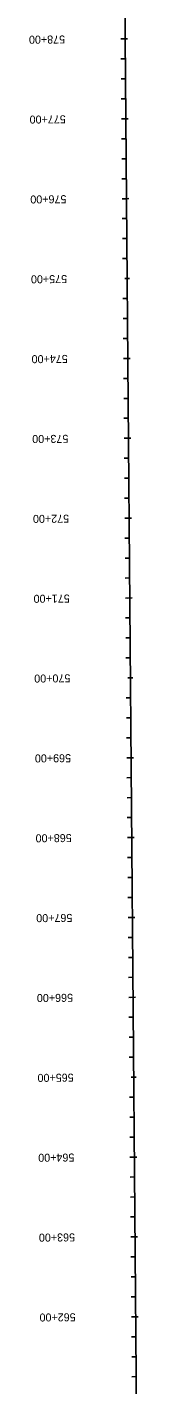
# Model space of a CAD drawing. Extents: x 23417911 to 23421158, y 6737892 to 6791804.
# Drawn here: x 23420741 to 23420889, y 6781685 to 6783385 of the extents above; entities that cross this region are included whole.
import ezdxf

# ---------------------------------------------------------------- set-up
doc = ezdxf.new("R2010")
doc.units = 0
for name, color, linetype in [('Alignment', 7, 'Continuous'), ('TextAlignmentLrg', 7, 'Continuous'), ('TextAlignmentSml', 7, 'Continuous')]:
    doc.layers.add(name, color=color, linetype=linetype)

msp = doc.modelspace()

# ---------------------------------------------------------------- linework, layer by layer
at = {"layer": 'Alignment'}
msp.add_line((23420888.7, 6779969.4), (23420840.8, 6785772.8), dxfattribs=at)
msp.add_line((23420888.7, 6779969.4), (23420840.8, 6785772.8), dxfattribs=at)
at = {"layer": 'TextAlignmentLrg'}
for p, q in [((23420860.7, 6783370.1), (23420855.2, 6783370.1)), ((23420861.5, 6783270.1), (23420856, 6783270.1)), ((23420862.3, 6783170.1), (23420856.8, 6783170.1)), ((23420860.1, 6783070.1), (23420866.2, 6783070.2)), ((23420864, 6782970.1), (23420858.5, 6782970.1)), ((23420864.8, 6782870.2), (23420859.3, 6782870.1)), ((23420865.6, 6782770.2), (23420860.1, 6782770.1)), ((23420866.4, 6782670.2), (23420861, 6782670.1)), ((23420864.2, 6782570.1), (23420870.3, 6782570.2)), ((23420868.1, 6782470.2), (23420862.6, 6782470.1)), ((23420868.9, 6782370.2), (23420863.4, 6782370.1)), ((23420869.7, 6782270.2), (23420864.3, 6782270.1)), ((23420870.6, 6782170.2), (23420865.1, 6782170.1)), ((23420868.3, 6782070.2), (23420874.4, 6782070.2)), ((23420872.2, 6781970.2), (23420866.7, 6781970.1)), ((23420873, 6781870.2), (23420867.6, 6781870.1)), ((23420873.9, 6781770.2), (23420868.4, 6781770.1))]:
    msp.add_line(p, q, dxfattribs=at)
at = {"layer": 'TextAlignmentSml'}
for p, q in [((23420857.6, 6783370.1), (23420863.7, 6783370.2)), ((23420860.9, 6783345.1), (23420855.4, 6783345.1)), ((23420861.1, 6783320.1), (23420855.6, 6783320.1)), ((23420861.3, 6783295.1), (23420855.8, 6783295.1)), ((23420858.4, 6783270.1), (23420864.5, 6783270.2)), ((23420861.7, 6783245.1), (23420856.2, 6783245.1)), ((23420861.9, 6783220.1), (23420856.4, 6783220.1)), ((23420862.1, 6783195.1), (23420856.6, 6783195.1)), ((23420859.2, 6783170.1), (23420865.4, 6783170.2)), ((23420862.5, 6783145.1), (23420857.1, 6783145.1)), ((23420862.7, 6783120.1), (23420857.3, 6783120.1)), ((23420862.9, 6783095.1), (23420857.5, 6783095.1)), ((23420860.1, 6783070.1), (23420866.2, 6783070.2)), ((23420863.3, 6783045.1), (23420857.9, 6783045.1)), ((23420863.5, 6783020.1), (23420858.1, 6783020.1)), ((23420863.8, 6782995.1), (23420858.3, 6782995.1)), ((23420860.9, 6782970.1), (23420867, 6782970.2)), ((23420864.2, 6782945.1), (23420858.7, 6782945.1)), ((23420864.4, 6782920.1), (23420858.9, 6782920.1)), ((23420864.6, 6782895.1), (23420859.1, 6782895.1)), ((23420861.7, 6782870.1), (23420867.8, 6782870.2)), ((23420865, 6782845.2), (23420859.5, 6782845.1)), ((23420865.2, 6782820.2), (23420859.7, 6782820.1)), ((23420865.4, 6782795.2), (23420859.9, 6782795.1)), ((23420862.5, 6782770.1), (23420868.7, 6782770.2)), ((23420865.8, 6782745.2), (23420860.4, 6782745.1)), ((23420866, 6782720.2), (23420860.6, 6782720.1)), ((23420866.2, 6782695.2), (23420860.8, 6782695.1)), ((23420863.4, 6782670.1), (23420869.5, 6782670.2)), ((23420866.6, 6782645.2), (23420861.2, 6782645.1)), ((23420866.8, 6782620.2), (23420861.4, 6782620.1)), ((23420867.1, 6782595.2), (23420861.6, 6782595.1)), ((23420864.2, 6782570.1), (23420870.3, 6782570.2)), ((23420867.5, 6782545.2), (23420862, 6782545.1)), ((23420867.7, 6782520.2), (23420862.2, 6782520.1)), ((23420867.9, 6782495.2), (23420862.4, 6782495.1)), ((23420865, 6782470.1), (23420871.1, 6782470.2)), ((23420868.3, 6782445.2), (23420862.8, 6782445.1)), ((23420868.5, 6782420.2), (23420863, 6782420.1)), ((23420868.7, 6782395.2), (23420863.2, 6782395.1)), ((23420865.8, 6782370.1), (23420872, 6782370.2)), ((23420869.1, 6782345.2), (23420863.7, 6782345.1)), ((23420869.3, 6782320.2), (23420863.9, 6782320.1)), ((23420869.5, 6782295.2), (23420864.1, 6782295.1)), ((23420866.7, 6782270.1), (23420872.8, 6782270.2)), ((23420869.9, 6782245.2), (23420864.5, 6782245.1)), ((23420870.1, 6782220.2), (23420864.7, 6782220.1)), ((23420870.4, 6782195.2), (23420864.9, 6782195.1)), ((23420867.5, 6782170.1), (23420873.6, 6782170.2)), ((23420870.8, 6782145.2), (23420865.3, 6782145.1)), ((23420871, 6782120.2), (23420865.5, 6782120.1)), ((23420871.2, 6782095.2), (23420865.7, 6782095.1)), ((23420868.3, 6782070.2), (23420874.4, 6782070.2)), ((23420871.6, 6782045.2), (23420866.1, 6782045.1)), ((23420871.8, 6782020.2), (23420866.3, 6782020.1)), ((23420872, 6781995.2), (23420866.5, 6781995.1)), ((23420869.1, 6781970.2), (23420875.3, 6781970.2)), ((23420872.4, 6781945.2), (23420867, 6781945.1)), ((23420872.6, 6781920.2), (23420867.2, 6781920.1)), ((23420872.8, 6781895.2), (23420867.4, 6781895.1)), ((23420870, 6781870.2), (23420876.1, 6781870.2)), ((23420873.2, 6781845.2), (23420867.8, 6781845.1)), ((23420873.4, 6781820.2), (23420868, 6781820.1)), ((23420873.7, 6781795.2), (23420868.2, 6781795.1)), ((23420870.8, 6781770.2), (23420876.9, 6781770.2)), ((23420874.1, 6781745.2), (23420868.6, 6781745.1)), ((23420874.3, 6781720.2), (23420868.8, 6781720.1)), ((23420874.5, 6781695.2), (23420869, 6781695.1))]:
    msp.add_line(p, q, dxfattribs=at)

# ---------------------------------------------------------------- texts
at = {"layer": 'TextAlignmentLrg'}
for s, p in [('575+00', (23420788.1, 6783074.5)), ('570+00', (23420792.2, 6782574.6)), ('565+00', (23420796.3, 6782074.6))]:
    msp.add_text(s, height=10.02, rotation=180.4726, dxfattribs=at).set_placement(p)
at = {"layer": 'TextAlignmentSml'}
for s, p in [('578+00', (23420785.6, 6783374.5)), ('577+00', (23420786.4, 6783274.5)), ('576+00', (23420787.3, 6783174.5)), ('575+00', (23420788.1, 6783074.5)), ('574+00', (23420788.9, 6782974.5)), ('573+00', (23420789.7, 6782874.5)), ('572+00', (23420790.6, 6782774.5)), ('571+00', (23420791.4, 6782674.5)), ('570+00', (23420792.2, 6782574.6)), ('569+00', (23420793, 6782474.6)), ('568+00', (23420793.9, 6782374.6)), ('567+00', (23420794.7, 6782274.6)), ('566+00', (23420795.5, 6782174.6)), ('565+00', (23420796.3, 6782074.6)), ('564+00', (23420797.2, 6781974.6)), ('563+00', (23420798, 6781874.6)), ('562+00', (23420798.8, 6781774.6))]:
    msp.add_text(s, height=10.02, rotation=180.4726, dxfattribs=at).set_placement(p)

doc.saveas('drawing.dxf')
